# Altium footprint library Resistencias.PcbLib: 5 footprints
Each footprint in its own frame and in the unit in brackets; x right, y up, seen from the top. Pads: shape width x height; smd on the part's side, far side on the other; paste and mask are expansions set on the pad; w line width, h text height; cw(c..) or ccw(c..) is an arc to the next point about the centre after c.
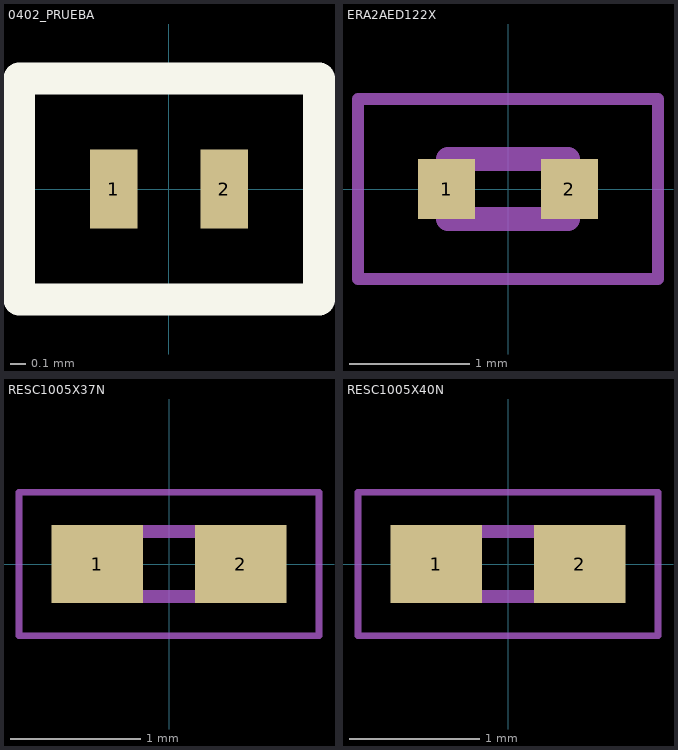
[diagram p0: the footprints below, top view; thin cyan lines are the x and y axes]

## 0402_PRUEBA [mm]
pads (2):
  rect 0.3x0.5 smd: 1(-0.35,0) 2(0.35,0)
Top Overlay:
  lines w0.2: -0.95,-0.7 0.95,-0.7 0.95,0.7 -0.95,0.7 -0.95,0 -0.95,-0.7
3D body: height 0.25, standoff 0, extent -0.254,-0.254 0.254,0.254
3D body: height 0.25, standoff 0, extent 0.254,-0.254 0.381,0.254
3D body: height 0.25, standoff 0, extent -0.381,-0.254 -0.254,0.254

## ERA2AED122X [mm]
pads (2):
  rect 0.475x0.5 smd: 1(-0.512,0) 2(0.512,0)
Mechanical 13:
  lines w0.2: -0.5,-0.25 -0.5,0.25 0.5,0.25 0.5,-0.25 -0.5,-0.25
Mechanical 15:
  lines w0.1: -1.25,-0.75 -1.25,0.75 1.25,0.75 1.25,-0.75 -1.25,-0.75
3D body "ERA-2ARC102X.stp": height 0.35, standoff 0, extent -0.5,-0.25 0.5,0.25

## PCBComponent_1 [mm]

## RESC1005X37N [mm]
pads (2):
  rect 0.7x0.6 smd: 1(-0.55,0) 2(0.55,0)
Mechanical 13:
  lines w0.1: -0.5,-0.25 -0.5,0.25 0.5,0.25 0.5,-0.25 -0.5,-0.25
Mechanical 15:
  lines w0.05: -1.15,-0.55 -1.15,0.55 1.15,0.55 1.15,-0.55 -1.15,-0.55
3D body "MCS04020C4701FE000.stp": height 0.32, standoff 0, extent -0.5,-0.25 0.5,0.25

## RESC1005X40N [mm]
pads (2):
  rect 0.7x0.6 smd: 1(-0.55,0) 2(0.55,0)
Mechanical 13:
  lines w0.1: -0.512,-0.25 -0.512,0.25 0.512,0.25 0.512,-0.25 -0.512,-0.25
Mechanical 15:
  lines w0.05: -1.15,-0.55 -1.15,0.55 1.15,0.55 1.15,-0.55 -1.15,-0.55
3D body "RK73B1ETTP103J.stp": height 0.4, standoff 0, extent -0.513,-0.25 0.513,0.25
